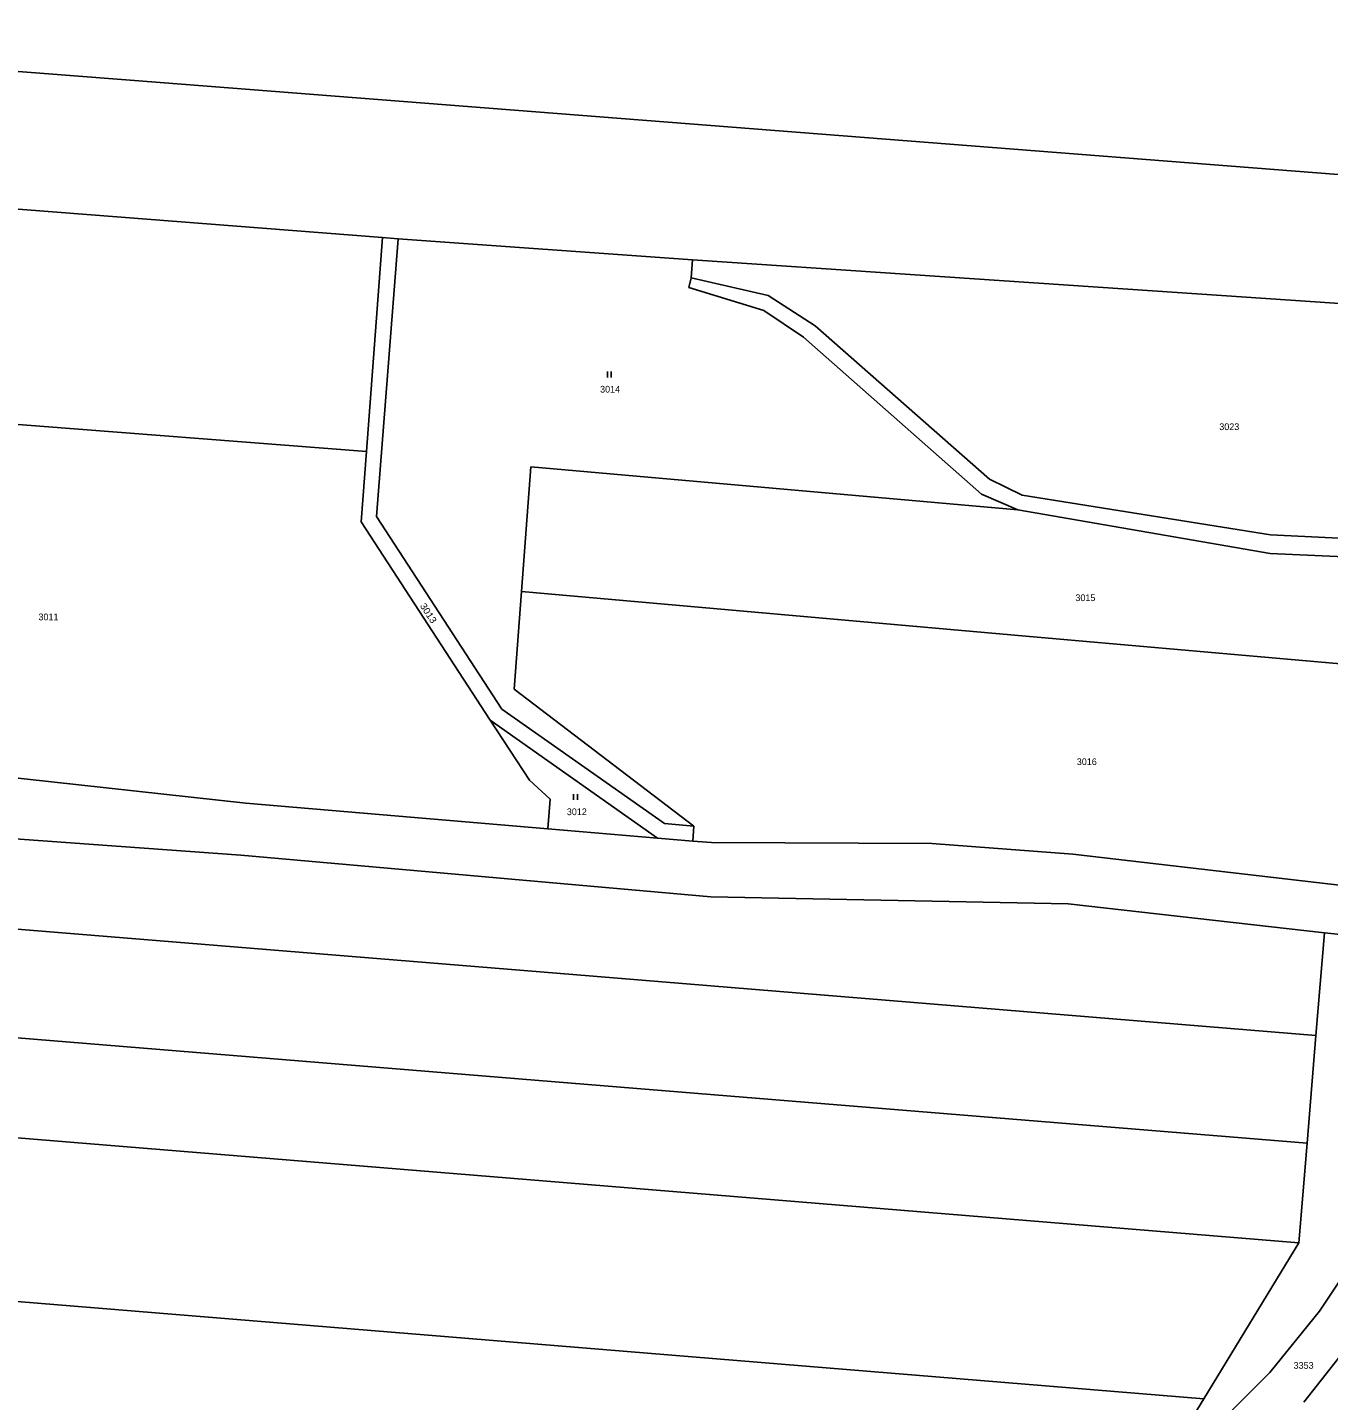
# Model space of a CAD drawing. Extents: x -618848 to -615803, y -1044450 to -1042254.
# Drawn here: x -617807.4 to -617478.1, y -1043290.2 to -1042942.7 of the extents above; entities that cross this region are included whole.
import ezdxf

# ---------------------------------------------------------------- set-up
doc = ezdxf.new("R2010")
doc.units = 0
doc.header["$LTSCALE"] = 0.68
doc.layers.add('1', color=7, linetype='Continuous', lineweight=25)
doc.layers.add('3', color=7, linetype='Continuous', lineweight=25)
doc.layers.add('2', color=7, linetype='Continuous')

msp = doc.modelspace()

# ---------------------------------------------------------------- linework, layer by layer
at = {"layer": '1'}
for p, q in [((-617952, -1042942.68), (-617773.78, -1042956.6)), ((-617773.78, -1042956.6), (-617595.55, -1042970.52)), ((-617595.55, -1042970.52), (-617417.33, -1042984.44)), ((-617717.57, -1042995.84), (-617878.01, -1042983.31)), ((-617721.62, -1043050.03), (-617717.57, -1042995.84)), ((-617713.58, -1042996.13), (-617719.06, -1043066.42)), ((-617713.58, -1042996.13), (-617717.57, -1042995.84)), ((-617639.07, -1043001.47), (-617713.58, -1042996.13)), ((-617639.07, -1043001.47), (-617639.43, -1043006.07)), ((-617528.9, -1043008.9), (-617639.07, -1043001.47)), ((-617640.04, -1043008.45), (-617639.43, -1043006.07)), ((-617621, -1043014.34), (-617640.04, -1043008.45)), ((-617639.43, -1043006.07), (-617619.98, -1043010.53)), ((-617619.98, -1043010.53), (-617608.04, -1043018.19)), ((-617418.74, -1043016.34), (-617528.9, -1043008.9)), ((-617611.02, -1043021.07), (-617621, -1043014.34)), ((-617608.04, -1043018.19), (-617563.94, -1043057.01)), ((-617565.93, -1043060.76), (-617611.02, -1043021.07)), ((-617910.7, -1043035.25), (-617721.62, -1043050.03)), ((-617722.94, -1043067.79), (-617721.62, -1043050.03)), ((-617682.34, -1043085.38), (-617679.99, -1043053.86)), ((-617679.99, -1043053.86), (-617556.8, -1043064.77)), ((-617563.94, -1043057.01), (-617555.63, -1043061.04)), ((-617556.8, -1043064.77), (-617565.93, -1043060.76)), ((-617555.63, -1043061.04), (-617492.79, -1043071.09)), ((-617690.25, -1043118.01), (-617722.94, -1043067.79)), ((-617719.06, -1043066.42), (-617687.32, -1043115.18)), ((-617492.92, -1043075.77), (-617556.8, -1043064.77)), ((-617492.79, -1043071.09), (-617418.27, -1043074.77)), ((-617419.46, -1043079.18), (-617492.92, -1043075.77)), ((-617682.34, -1043085.38), (-617684.19, -1043110.15)), ((-617554.76, -1043096.68), (-617682.34, -1043085.38)), ((-617427.17, -1043107.98), (-617554.76, -1043096.68)), ((-617638.71, -1043144.78), (-617684.19, -1043110.15)), ((-617687.32, -1043115.18), (-617646.19, -1043144.15)), ((-617690.25, -1043118.01), (-617680.36, -1043133.2)), ((-617647.93, -1043147.82), (-617690.25, -1043118.01)), ((-617822.86, -1043131.18), (-617752.14, -1043139.02)), ((-617680.36, -1043133.2), (-617675.07, -1043138)), ((-617752.14, -1043139.02), (-617675.7, -1043145.48)), ((-617675.07, -1043138), (-617675.7, -1043145.48)), ((-617646.19, -1043144.15), (-617638.71, -1043144.78)), ((-617821.55, -1043147.25), (-617753.4, -1043152.1)), ((-617675.7, -1043145.48), (-617647.93, -1043147.82)), ((-617638.71, -1043144.78), (-617639.02, -1043148.57)), ((-617639.02, -1043148.57), (-617647.93, -1043147.82)), ((-617639.02, -1043148.57), (-617634.27, -1043148.97)), ((-617634.27, -1043148.97), (-617578.49, -1043149.17)), ((-617578.49, -1043149.17), (-617542.83, -1043151.92)), ((-617753.4, -1043152.1), (-617634.45, -1043162.69)), ((-617542.83, -1043151.92), (-617466.23, -1043160.76)), ((-617634.45, -1043162.69), (-617544.06, -1043164.42)), ((-617544.06, -1043164.42), (-617479.19, -1043171.76)), ((-617857.38, -1043166.99), (-617669.35, -1043182.38)), ((-617479.19, -1043171.76), (-617481.32, -1043197.78)), ((-617479.19, -1043171.76), (-617463.07, -1043173.59)), ((-617669.35, -1043182.38), (-617481.32, -1043197.78)), ((-617673.82, -1043209.48), (-617864.1, -1043193.9)), ((-617481.32, -1043197.78), (-617483.55, -1043225.06)), ((-617483.55, -1043225.06), (-617673.82, -1043209.48)), ((-617866.21, -1043219.07), (-617675.91, -1043234.65)), ((-617483.55, -1043225.06), (-617485.61, -1043250.24)), ((-617675.91, -1043234.65), (-617485.61, -1043250.24)), ((-617485.61, -1043250.24), (-617509.65, -1043289.72)), ((-617480.44, -1043267.57), (-617469.85, -1043251.63)), ((-617695.68, -1043274.49), (-617881.71, -1043259.25)), ((-617493, -1043283.07), (-617480.44, -1043267.57)), ((-617468.72, -1043270.64), (-617484.37, -1043290.59)), ((-617509.65, -1043289.72), (-617695.68, -1043274.49)), ((-617525.45, -1043315.37), (-617493, -1043283.07)), ((-617509.65, -1043289.72), (-617525.45, -1043315.37))]:
    msp.add_line(p, q, dxfattribs=at)
at = {"layer": '3'}
for p, q in [((-617660.641, -1043031.28), (-617660.641, -1043029.78)), ((-617659.64, -1043031.28), (-617659.64, -1043029.78)), ((-617669.191, -1043138.18), (-617669.191, -1043136.68)), ((-617668.19, -1043138.18), (-617668.19, -1043136.68))]:
    msp.add_line(p, q, dxfattribs=at)

# ---------------------------------------------------------------- texts
at = {"layer": '2'}
for s, p in [('3014', (-617662.47, -1043035.075)), ('3023', (-617505.78, -1043044.575)), ('3015', (-617542.19, -1043087.845)), ('3011', (-617804.6, -1043092.695)), ('3016', (-617541.84, -1043129.345)), ('3012', (-617670.89, -1043142.015)), ('3353', (-617486.97, -1043282.115))]:
    msp.add_text(s, height=1.7, dxfattribs=at).set_placement(p)
at = {"layer": '2', "width": 1.1}
msp.add_text('3013', height=1.7, rotation=303, dxfattribs=at).set_placement((-617708.146, -1043089.031))

doc.saveas('drawing.dxf')
